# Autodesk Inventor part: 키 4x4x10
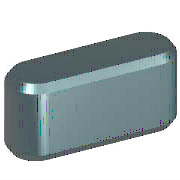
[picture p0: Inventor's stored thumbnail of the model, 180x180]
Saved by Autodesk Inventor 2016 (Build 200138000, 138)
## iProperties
IsCustomPart: 1
Created: 2012-02
Part Number: 키 4x4x10
Material: 강철, 연강
Description: 키 및 해당 키홈
Document SubType Name: Modeling
Standard: KS B 1311
Designer: test
Standards Organization: KS
Language: ko-KR
Size Designation: 4 x 4 x 10
Categories: <MemberInstance><Categories><Category DisplayName="샤프트 부품" InternalName="7f7aeb1f-a693-4053-b835-cee3144e0d98" Mnemonic="SHFT"><Category DisplayName="키" Interna
Density: 1 g/cm^3
Appearance: 노란색
Author: test
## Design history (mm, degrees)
workplane "Work Plane1"
workplane "Work Plane2"
sketch "스케치1"
  geometry: L1 (2, 2)-(8, 2); L2 (8, -2)-(2, -2); L3 (0, 9.4)-(0, -7.4) reference; L4 (-5, 0)-(30, 0) reference; L5 (10, 0)-(10, 7); A1 r 2 centre (2, 0) between (2, 2) and (2, -2); A2 r 2 centre (8, 0) between (8, -2) and (8, 2)
  constraints: 6 end point, 5 point on circle, 4 tangent, 3 point on line, 2 centre point, 1 horizontal, 1 parallel, 1 perpendicular
  dimensions: "d0" = 2 radius of A1 (= 0.5 x PB); "d13" = 2 radius of A2 (= 0.5 x PB); "d14" = 10 distance between parallel lines of L5 L3 (= NLG)
extrude "본체1" new body sketch "스케치1" taper "d3" = 0 deg; stored distance "d4" = 10
workplane "Work Plane3"
node "작업 평면4"
body "Solid1"
chamfer "모따기1" distance "d8" = 0.25 (= PHH); stored, may be unused: second distance "d9" = 0.25 (= PHH), angle "d15" = 45 deg
other parameters: "d1" = -2.5 (= -PNT), "d2" = 1.5 (= PH - PNT), "NLG" = 10 [user parameter; used in 3 equation terms], "PB" = 4 [user parameter; used in 2 equation terms], "PNT" = 2.5 [user parameter; used in 2 equation terms], "PH" = 4 [user parameter; used in 1 equation term], "PHH" = 0.25 [user parameter; used in 2 equation terms], "d10" = 0, "d16" = 0, "d17" = 0, "d18" = 0, "WDMAX" = 12 [user parameter], "RR" = 0.08 [user parameter], "PUEB" = 1.8 [user parameter], "d19" = 5
